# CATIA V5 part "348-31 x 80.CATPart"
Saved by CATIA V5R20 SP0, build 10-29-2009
Part number: 348-31 x 80
Definition: NONE
Nomenclature: 348-31 x 80
Source: Unknown
Description: 348-31 x 80
Bounding box of the stored display mesh (mm): x 0 to 80, y -22.5 to 22.5, z -22.5 to 22.5
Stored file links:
  C:\Users\Utente\Desktop\IO LAVORO\3D X SITO CF\X SITO\3D files 348\348-31 x 80.CATPart
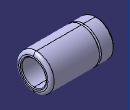
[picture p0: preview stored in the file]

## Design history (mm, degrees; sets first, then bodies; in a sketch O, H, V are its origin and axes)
Body1 "348-31 x 80" (main body)
  Solid1: solid without history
